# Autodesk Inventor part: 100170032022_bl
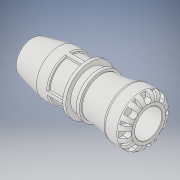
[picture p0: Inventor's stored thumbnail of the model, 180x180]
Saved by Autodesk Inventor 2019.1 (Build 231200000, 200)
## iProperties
Created: 2016-12
Part Number: 100170032022_bl
Material: PVC-Piping
Description: PLASSON UNIVERSAL COUPLING 19-22X32 SERIES 1
Document SubType Name: Modeling
Designer: KIM
Mass: 298.996 g
Surface Area: 569.061 cm^2
Volume: 213.568 cm^3
Density: 1.4 g/cm^3
Appearance: Smooth - White
Author: KIM
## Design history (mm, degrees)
derived "10017.ipt"
feature "Solid1::10017.ipt" dims "ScaleForDerivedMember" = 10
tag "TaggingFeature1"
body "Solid1"
other parameters: "d92" = 8.8 [user parameter], "d94" = 57.6 [user parameter], "d15" = 22 [user parameter], "d16" = 21.56 [user parameter], "d20" = 46.74 [user parameter], "d21" = 80 deg [user parameter], "d22" = 19.71429 [user parameter], "d23" = 0 [user parameter], "d25" = 360 deg [user parameter], "d48" = 1.6 [user parameter], "d52" = 0.57 [user parameter], "d72" = 32 [user parameter], "d73" = 55 [user parameter], "d74" = 3.2 [user parameter], "d80" = 23.1 [user parameter], "d81" = 77 deg [user parameter], "d82" = 138 [user parameter], "d83" = 69 [user parameter], "d84" = 47 [user parameter], "d85" = 3.66667 [user parameter], "d86" = 57 [user parameter], "d87" = 52.44 [user parameter], "d88" = 57.6 [user parameter], "d89" = 9.4 [user parameter], "d90" = 45.6 [user parameter], "d91" = 46.08 [user parameter], "d93" = 1.38 [user parameter], "d96" = 7.04 [user parameter], "d97" = 7.04 [user parameter], "d98" = 0 [user parameter], "d100" = 360 deg [user parameter], "d103" = 0.64 [user parameter], "d104" = 0.64 [user parameter], "d105" = 8 deg [user parameter], "d106" = 8 deg [user parameter], "d108" = 0 [user parameter], "d110" = 360 deg [user parameter], "d112" = 9.6 [user parameter], "d113" = 4.8 [user parameter], "d115" = 44 [user parameter], "d116" = 0 [user parameter], "d118" = 360 deg [user parameter], "d120" = 5.7 [user parameter], "d121" = 0.57 [user parameter], "d_" = 32 [user parameter], "E_" = 57 [user parameter], "H_" = 138 [user parameter], "l_" = 55 [user parameter], "d_1" = 22 [user parameter], "l_1" = 47 [user parameter], "d66" = 76 [user parameter], "d68" = 41 [user parameter], "d69" = 45 [user parameter], "d70" = 20.955 [user parameter], "d71" = 13 [user parameter]
